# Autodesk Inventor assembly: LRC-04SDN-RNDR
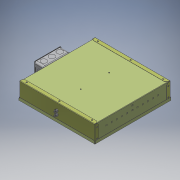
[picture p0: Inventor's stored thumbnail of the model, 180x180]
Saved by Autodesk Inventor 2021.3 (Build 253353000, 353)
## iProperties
Part Number: LRC-04SDN-RNDR
Document SubType Name: Assembly
Designer: JChurch
description: 0:0:Super Shallow 4" Downlight
manufacturer: 0:0:The Kirlin Company
model: 0:0:LRC-04SDN
url: 0:0:
load_classification: Lighting
motor: 0 ul
Author: JChurch
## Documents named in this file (6)
- X:\Revit Files\0000-Un-Zipped\COB\LRC-04SDN-RND\LRC-04SDN-RNDR.iam
- X:\INVENTOR\830\830520-00-00.ipt
- X:\INVENTOR\885\885000-00-00.iam
- X:\INVENTOR\750\750031-00-XX.iam
- X:\INVENTOR\725\725377-00-00.ipt
- X:\Revit Files\0000-Un-Zipped\COB\LRC-04SDN-RND\LRC-04SDN-RNDR_Substitute_1.ipt
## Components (5 placed, 5 different names)
1. 830520-00-00:1 — Mate:1, Mate:2, Mate:3, Mate:4, Mate:5, Angle:1, Insert:2
2. 885000-00-00:1 [sub-assembly] — Mate:4, Mate:5, Angle:1
3. 750031-00-XX:1 [sub-assembly] — Insert:1, Insert:2
4. 725377-00-00:1 — Insert:1
5. LRC-04SDN-RNDR_Substitute_1:1
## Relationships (8: Mate 5, Insert 2, Angle 1)
- Mate:1: 830520-00-00:1
- Mate:2: 830520-00-00:1
- Mate:3: 830520-00-00:1
- Mate:4: 830520-00-00:1 ↔ 885000-00-00:1
- Mate:5: 830520-00-00:1 ↔ 885000-00-00:1
- Angle:1: 830520-00-00:1 ↔ 885000-00-00:1
- Insert:1: 750031-00-XX:1 ↔ 725377-00-00:1
- Insert:2: 830520-00-00:1 ↔ 750031-00-XX:1
